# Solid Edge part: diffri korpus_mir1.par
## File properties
Author: Türk
Template: Iso Part.par
Last saved by: Türk
Revision: 5
Application: Solid Edge
Accuracy: 0,990
Username: Türk
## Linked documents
diffri korpus.par
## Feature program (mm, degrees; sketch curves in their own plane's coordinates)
part copy "CopiedPart_1"
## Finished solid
Body 1: solid body, 102 faces, 277 edges, 173 vertices.
  Faces by surface: plane 67, cylinder 35
  Edges by curve: line 180, circle 75, ellipse 16, intersection 6
Bounding box of the edges (mm): 315.000 x 120.000 x 267.500, from (-157.5, -120, -105) to (157.5, 0, 162.5).
Cylindrical faces by radius (mm): R5 x2, R7.5 x4, R20 x4, R25 x4, R27.5 x3, R40 x4, R50 x6, R52.5 x3, R100 x4, R102.5 x1
Planar faces by outward normal: +x 12, +y 8, +z 10, -x 13, -y 4, -z 12, oblique 8
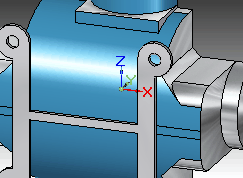
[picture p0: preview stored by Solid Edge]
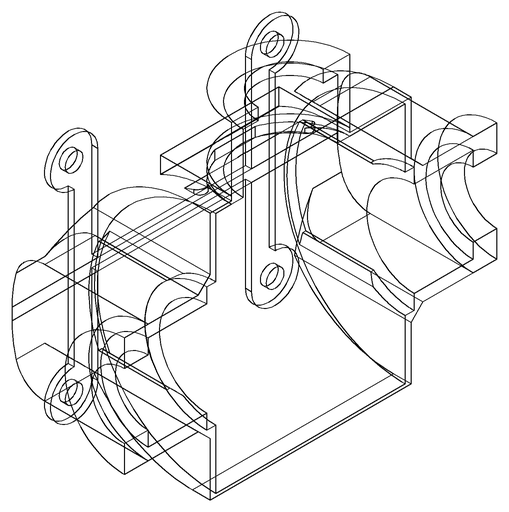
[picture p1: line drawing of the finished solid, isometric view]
